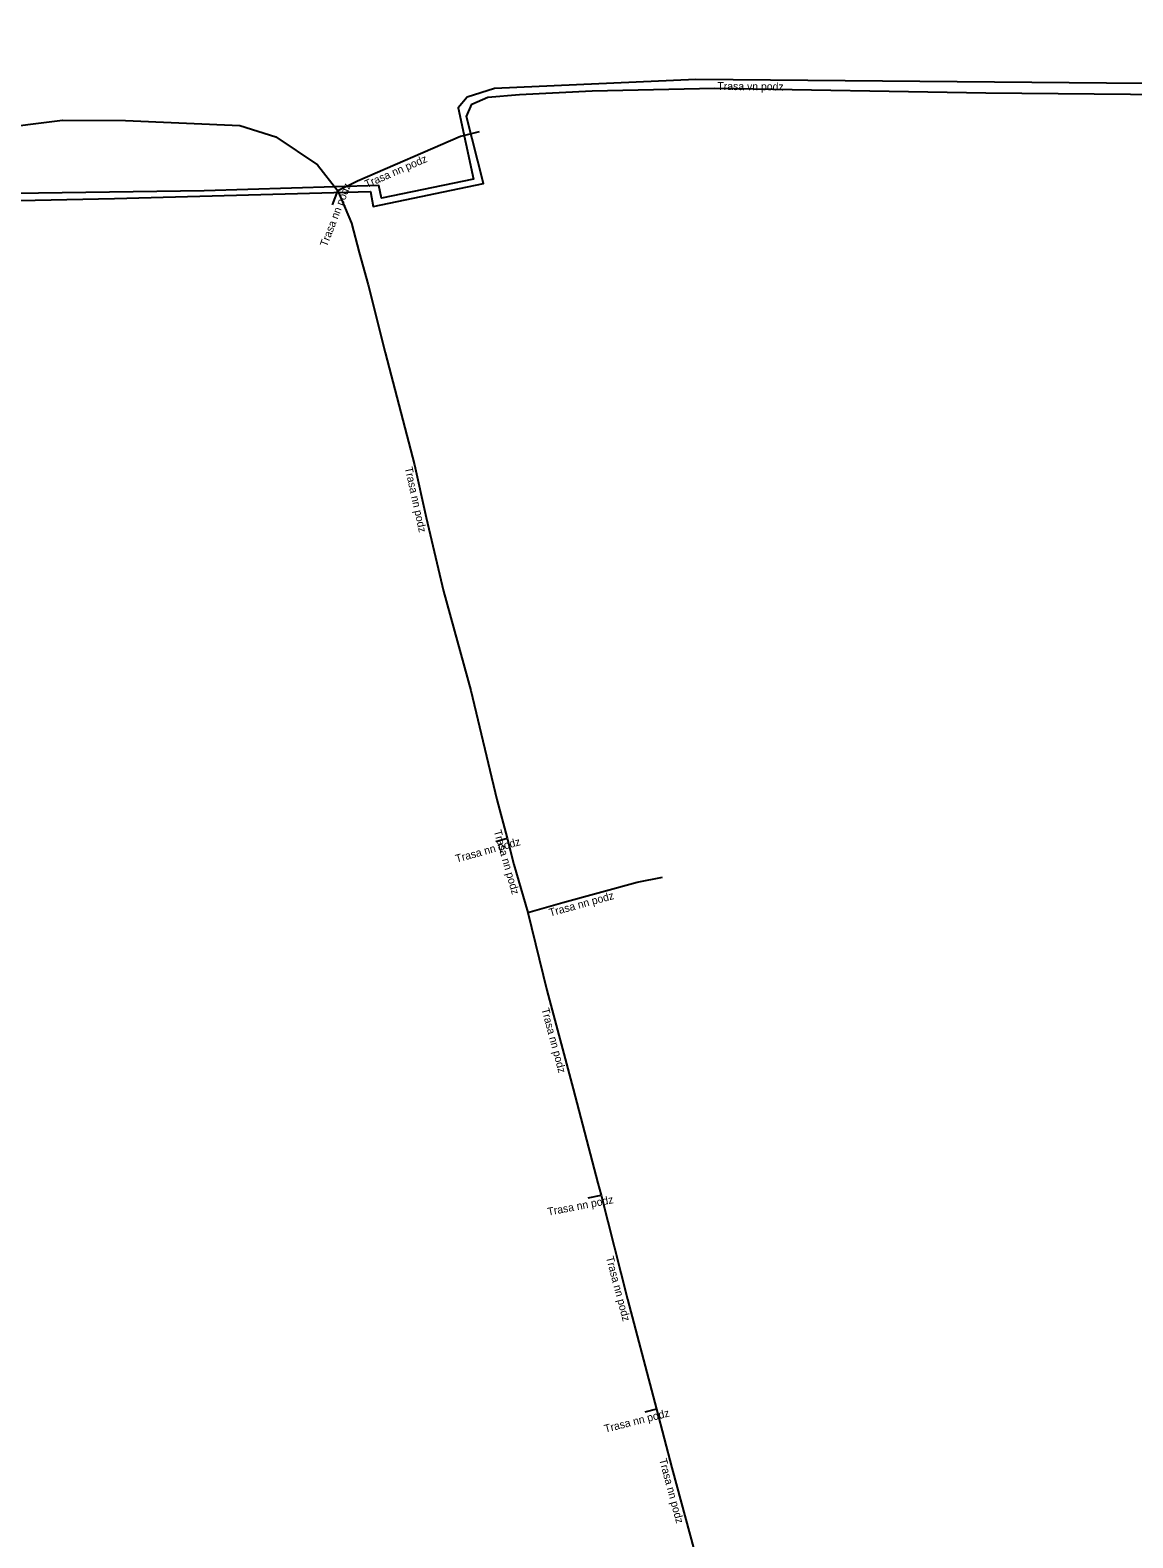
# Model space of a CAD drawing. Extents: x -756855 to -756032, y -1046964 to -1046550.
# Drawn here: x -756373.9 to -756303.4, y -1046678 to -1046581.6 of the extents above; entities that cross this region are included whole.
import ezdxf

# ---------------------------------------------------------------- set-up
doc = ezdxf.new("R2010")
doc.units = 0
for name, color, linetype in [('Popiskový text - Ostatní atributy Trasy', 7, 'Continuous'), ('Spojnice NN', 7, 'Continuous'), ('Spojnice VN', 7, 'Continuous')]:
    doc.layers.add(name, color=color, linetype=linetype)

msp = doc.modelspace()

# ---------------------------------------------------------------- linework, layer by layer
at = {"layer": 'Spojnice NN'}
for points in [[(-756394.79, -1046581.56), (-756394.23, -1046583.53), (-756393.4, -1046587.66), (-756392.89, -1046590.36), (-756392.43, -1046590.71), (-756391.9, -1046591.07), (-756390.78, -1046591.49), (-756385.81, -1046590.16), (-756382.48, -1046589.11), (-756376.43, -1046587.9), (-756371.83, -1046587.31), (-756367.8, -1046587.34), (-756360.49, -1046587.65), (-756358.19, -1046588.39), (-756355.52, -1046590.18), (-756354.22, -1046591.83)], [(-756345.2, -1046588.06), (-756346.4, -1046588.36), (-756352.98, -1046591.21), (-756354.22, -1046591.83)], [(-756354.57, -1046592.73), (-756354.22, -1046591.83)], [(-756354.22, -1046591.83), (-756353.35, -1046593.91), (-756352.86, -1046595.77), (-756352.29, -1046597.84), (-756351.21, -1046602.18), (-756349.33, -1046609.35), (-756348.59, -1046612.71), (-756347.48, -1046617.43), (-756345.73, -1046623.79), (-756344.07, -1046630.75), (-756343.41, -1046633.23)], [(-756344.14, -1046633.43), (-756343.41, -1046633.23)], [(-756343.41, -1046633.23), (-756342.98, -1046634.9), (-756342.09, -1046637.98)], [(-756342.09, -1046637.98), (-756339.85, -1046637.34), (-756335.09, -1046636.03), (-756333.47, -1046635.71)], [(-756342.09, -1046637.98), (-756340.87, -1046642.95), (-756339.18, -1046649.26), (-756337.61, -1046655.28), (-756337.4, -1046656.05)], [(-756338.23, -1046656.21), (-756337.4, -1046656.05)], [(-756337.4, -1046656.05), (-756335.72, -1046662.7), (-756334.08, -1046668.92), (-756333.87, -1046669.74)], [(-756333.87, -1046669.74), (-756334.62, -1046669.93)], [(-756333.87, -1046669.74), (-756332.89, -1046673.48), (-756330.61, -1046681.9)]]:
    msp.add_lwpolyline(points, dxfattribs=at)
at = {"layer": 'Spojnice VN'}
for points in [[(-756223.24, -1046585.74), (-756223.44, -1046585.74), (-756234.854, -1046585.278), (-756246.587, -1046585.278), (-756278.85, -1046585.193), (-756331.347, -1046584.718), (-756344.208, -1046585.283), (-756345.966, -1046585.847), (-756346.53, -1046586.525), (-756345.564, -1046591.094), (-756351.445, -1046592.308), (-756351.607, -1046591.493), (-756362.775, -1046591.832), (-756379.431, -1046592.061), (-756389.359, -1046591.609), (-756390.262, -1046591.722), (-756403.799, -1046596.238), (-756407.605, -1046585.018), (-756412.541, -1046587.418), (-756413.242, -1046585.898)], [(-756379.665, -1046592.559), (-756368.496, -1046592.333), (-756352.138, -1046591.882), (-756351.978, -1046592.841), (-756344.927, -1046591.373), (-756345.999, -1046587.082), (-756345.661, -1046586.292), (-756344.645, -1046585.84), (-756342.615, -1046585.671), (-756337.982, -1046585.445), (-756330.141, -1046585.275), (-756312.823, -1046585.557), (-756278.17, -1046585.896)]]:
    msp.add_lwpolyline(points, dxfattribs=at)

# ---------------------------------------------------------------- texts
at = {"layer": 'Popiskový text - Ostatní atributy Trasy'}
for s, rotation, p in [('Trasa vn podz', 359.48159, (-756329.975, -1046585.381)), ('Trasa nn podz', 23.41892, (-756352.389, -1046591.662)), ('Trasa nn podz', 68.74949, (-756354.93, -1046595.449)), ('Trasa nn podz', 282.42043, (-756349.954, -1046609.54)), ('Trasa nn podz', 286.11723, (-756344.273, -1046632.768)), ('Trasa nn podz', 15.32151, (-756346.639, -1046634.789)), ('Trasa nn podz', 15.38744, (-756340.659, -1046638.237)), ('Trasa nn podz', 284.99357, (-756341.221, -1046644.151)), ('Trasa nn podz', 10.91113, (-756340.782, -1046657.364)), ('Trasa nn podz', 284.77076, (-756337.097, -1046660.025)), ('Trasa nn podz', 14.21585, (-756337.137, -1046671.238)), ('Trasa nn podz', 285.15143, (-756333.705, -1046672.956))]:
    msp.add_text(s, height=0.5, rotation=rotation, dxfattribs=at).set_placement(p)

doc.saveas('drawing.dxf')
